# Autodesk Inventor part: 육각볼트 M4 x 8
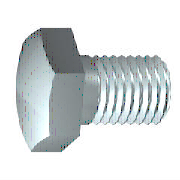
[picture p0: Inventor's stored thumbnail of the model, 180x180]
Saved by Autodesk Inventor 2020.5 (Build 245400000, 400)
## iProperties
Created: 2012-02
Part Number: 육각볼트 M4 x 8
Material: 강철, 연강
Description: 6각 머리 나사
Document SubType Name: Modeling
Standard: ISO 4017
Designer: mduedu
Standard Revision: Third edition 1999-08-15
Standards Organization: ISO
Language: ko-KR
Size Designation: M4 x 10
Categories: <MemberInstance><Categories><Category DisplayName="조임쇠" InternalName="e4da775c-781d-43d5-af7c-5136215cf5a6" Mnemonic="FSTN"><Category DisplayName="볼트" InternalN
Density: 7.86 g/cm^3
Appearance: 반광택
IsCustomPart: 0
Author: mduedu
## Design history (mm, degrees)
sketch "스케치1"
  geometry: L1 (0, 3.015)-(0, 2); L2 (1.75, 2)-(8, 2); L3 (8, 2)-(8, 0); L4 (8, 0)-(-0.4, 0); L5 (-2.08, 0)-(9.68, 0) reference; L6 (-0.4, 0)-(-0.4, 3.015); L7 (-0.4, 3.015)-(0, 3.015); L8 (1.75, 2)-(1.32, 2); L9 (1.32, 2)-(0, 2); L10 (0, -0.603)-(0, 3.618) reference
  constraints: 16 end point, 2 collinear, 2 perpendicular, 1 parallel
  dimensions: "d0" = 8 distance between parallel lines of L3 L1 (= NLG); "d1" = 6.25 distance from line of L2.start L3 (= GEL); "d2" = 4 diameter of L2 L4 (= GD); "d9" = 0.4001 distance between parallel lines of L6 L1 (computed from SD); "d10" = 6.03 diameter of L7 L4 (= SD2); "d13" = 0.42952 distance of L2.start L8.end (computed from GAL); "d14" = 4 diameter of L9 L4 (= BDM)
revolve "본체" sketch "스케치1" stored, may be unused: angle "d12" = 90 deg
sketch "스케치2"
  geometry: L1 (0, 4.041)-(3.5, 2.021); L2 (3.5, 2.021)-(3.5, -2.021); L3 (3.5, -2.021)-(0, -4.041); L4 (0, -4.041)-(-3.5, -2.021); L5 (-3.5, -2.021)-(-3.5, 2.021); L6 (-3.5, 2.021)-(0, 4.041); 2 further points
  constraints: 12 end point, 1 coincident, 1 vertical, 11 other
  dimensions: "d11" = 7 distance between parallel lines of L5 L2 (= SW)
extrude "머리" join sketch "스케치2" distance "d3" = 2.4 (= KOH - SD); taper "d4" = 0 deg
sketch "스케치4"
  geometry: L1 (-2.8, 3.5)-(-2.8, 4.041); L2 (-2.8, 4.041)-(-2.487, 4.041); L3 (-2.487, 4.041)-(-2.8, 3.5); L4 (-3.28, 0)-(0.08, 0) reference; L5 (-0.4, 4.041)-(-2.8, 4.041) reference; L6 (-2.8, 2.021)-(-2.8, 4.041) reference
  constraints: 6 end point, 2 collinear, 1 perpendicular, 1 vertical
  dimensions: "d5" = 30 deg angle of L3 L1 (= ANG1); "d19" = 7 diameter of L1.start L4 (= SW0)
revolve "모따기1" sketch "스케치4" stored, may be unused: angle "d21" = 90 deg
workplane "Work Plane1"
body "Solid1"
feature "스레드" dims "d15" = 6.25 (= GEL), "d16" = 0
chamfer "모따기2" distance "d6" = 0.42941 (= -0.5 x SPD + 0.5 x GD); stored, may be unused: second distance "d7" = 0.42952 (computed from GUL), angle "d55" = 45 deg
other parameters: "NLG" = 8 [user parameter; used in 1 equation term], "GD" = 4 (= NND) [user parameter; used in 2 equation terms], "BDM" = 4 (= NND) [user parameter; used in 1 equation term], "KOH" = 2.8 [user parameter; used in 1 equation term], "GEL" = 6.25 [user parameter; used in 2 equation terms], "SW" = 7 [user parameter; used in 2 equation terms], "SW0" = 7 (= SW) [user parameter; used in 1 equation term], "SPD" = 3.14117 (= NND - 1.2269 x PTC) [user parameter; used in 1 equation term], "SD2" = 6.03 [user parameter; used in 2 equation terms], "SD" = 0.4 [user parameter; used in 2 equation terms], "ANG1" = 30 deg [user parameter; used in 1 equation term], "GAL" = 0.42941 (= 0.61345 x PTC) [user parameter; used in 1 equation term], "GUL" = 0.42941 (= 0.61345 x PTC) [user parameter; used in 1 equation term], "d8" = 0, "RR" = 0.2 [user parameter], "d57" = 0, "d58" = 0, "TPU" = 14.28571 (computed from PTC) [user parameter], "GD1" = 3.14117 (= THREADDIA - 1.2269 x PTC) [user parameter], "THREADDIA" = 4 [user parameter; used in 1 equation term], "SDH" = 6.03 (= SD2) [user parameter], "SDHG" = 2.1 [user parameter], "TOA" = 30 deg [user parameter], "PTC" = 0.7 [user parameter; used in 5 equation terms], "NND" = 4 [user parameter; used in 3 equation terms], "E0" = 8.085 [user parameter]
